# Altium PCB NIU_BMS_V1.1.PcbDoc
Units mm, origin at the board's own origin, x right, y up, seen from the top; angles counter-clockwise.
Board outline 49.68 x 32.61 mm, 2 copper layers (Top Layer, Bottom Layer); 39 components, 16 nets, 111 pads, 19 vias.
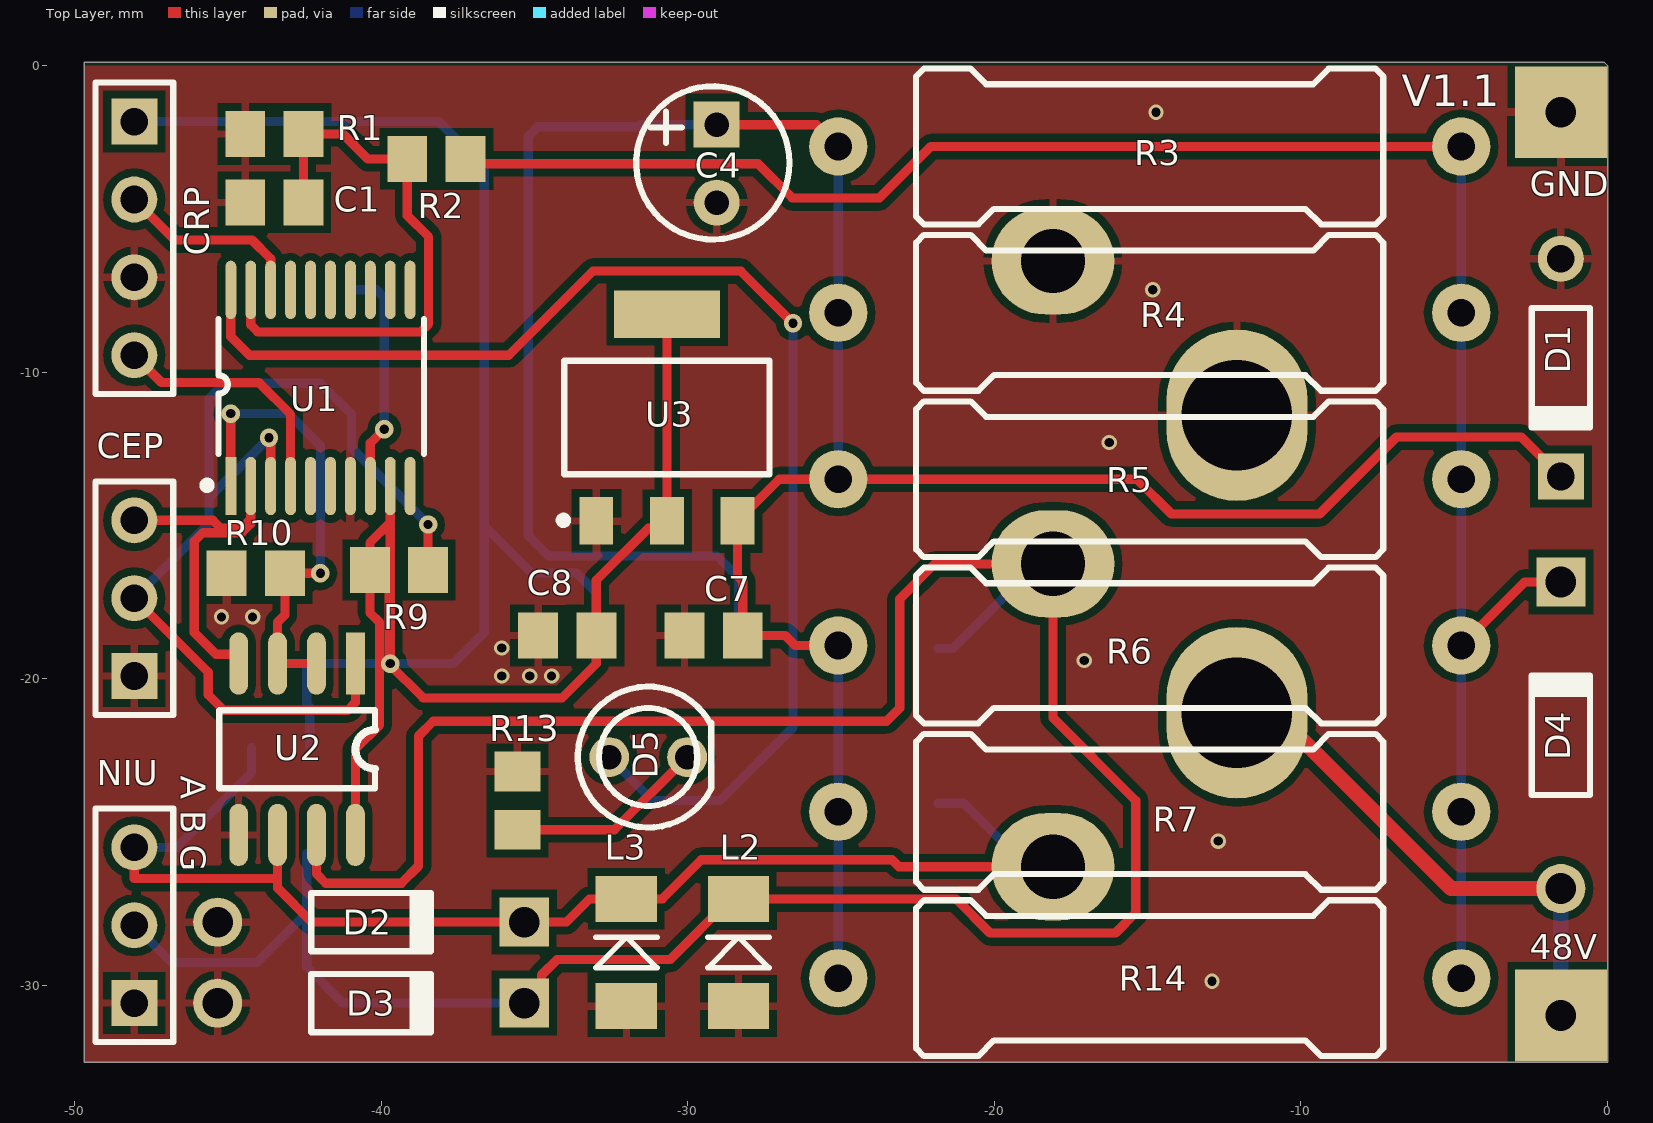
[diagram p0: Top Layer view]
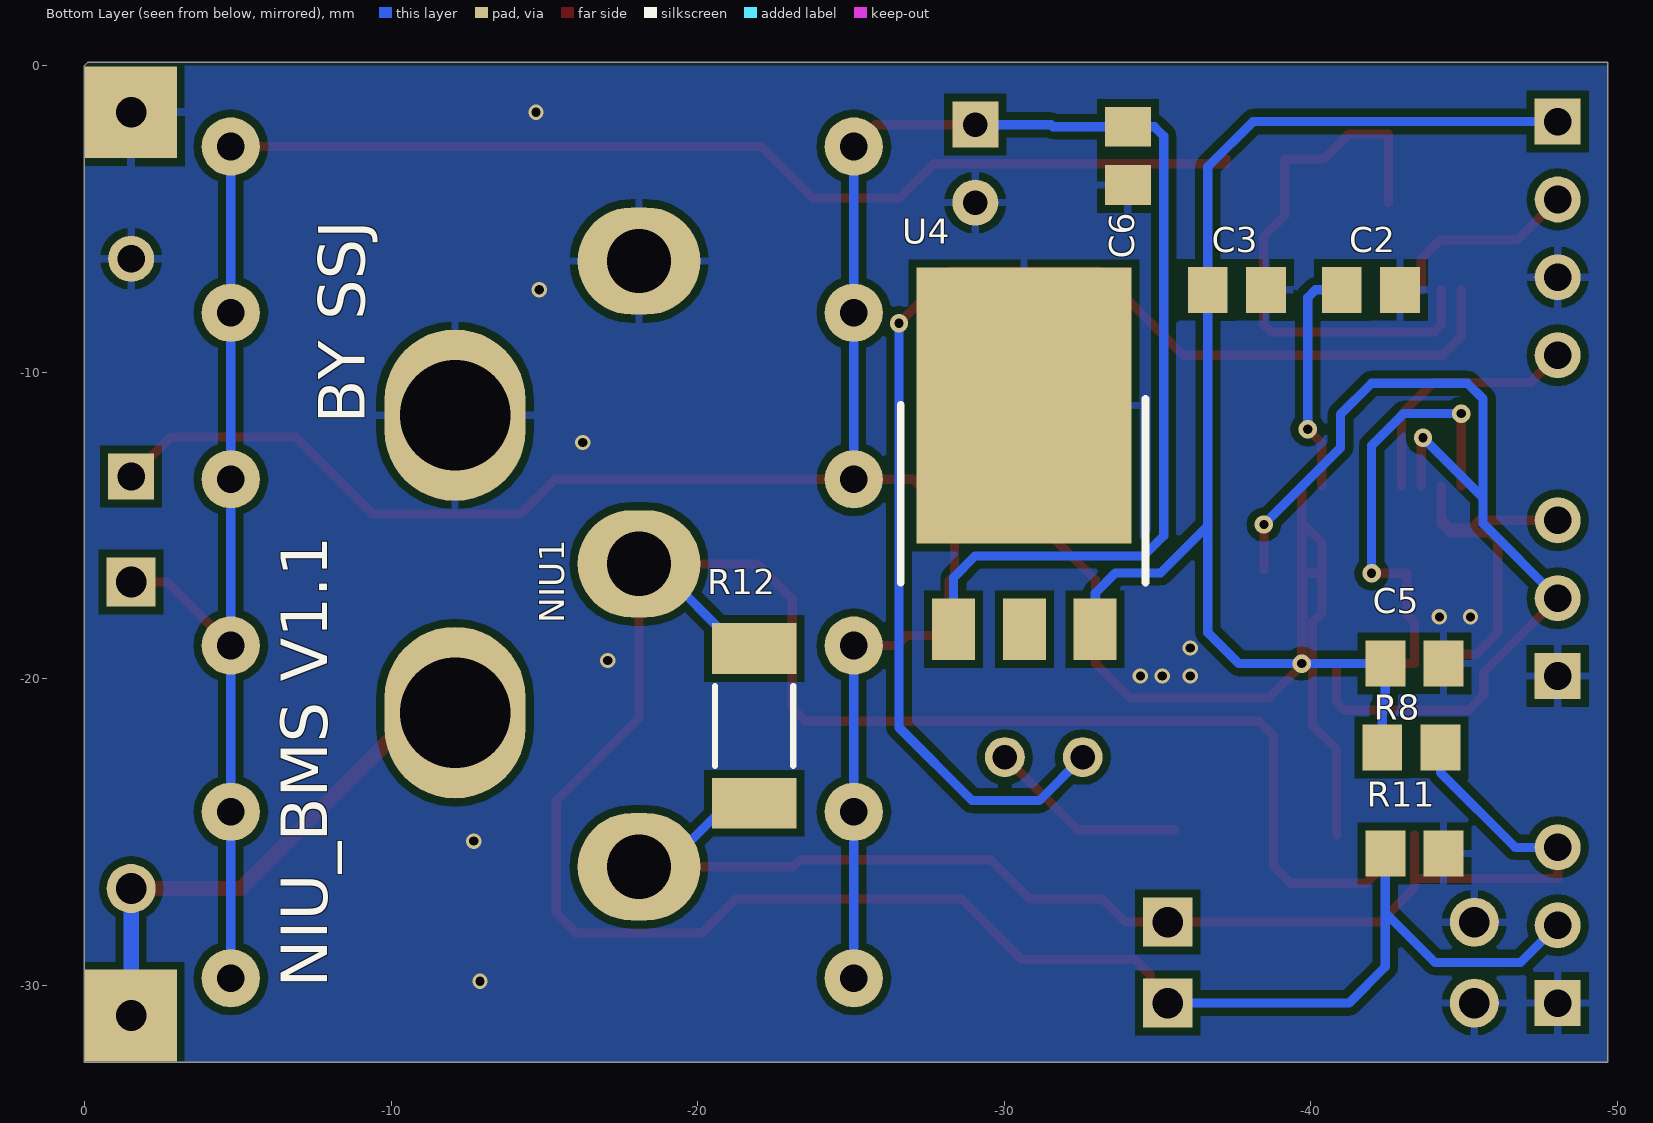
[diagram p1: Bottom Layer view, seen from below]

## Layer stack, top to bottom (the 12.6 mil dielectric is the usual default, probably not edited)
Top Layer: signal copper 0.0356
Dielectric: dielectric 0.32, FR-4, Dk 4.8
Bottom Layer: signal copper 0.0356

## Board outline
0,0 -0.102,0.102 -49.682,0.102 -49.682,-32.512 0,-32.512 0,0

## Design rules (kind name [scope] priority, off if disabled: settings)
Clearance [All] p1: gap=0.254
FabricationTestPointUsage TestPointUsage [All] p1: valid=0 allowmultiple=FALSE
FabricationTestpoint Testpoint [All] p1: side=3 testpointundercomponent=TRUE minsize=1.016 maxsize=2.54 preferedsize=1.524 minholesize=0 maxholesize=1.016 preferedholesize=0.813 testpointgrid=0.025 allowsidetop=TRUE allowsidebottom=TRUE usegrid=TRUE gridtolerance=0
PolygonConnect [All] p1: connectstyle=Relief reliefconductorwidth=0.254 reliefentries=4 polygonreliefangle="90 Angle"
RoutingVias [All] p1: holewidth=0.3 width=0.6 viastyle="Through Hole" minholewidth=0.3 minwidth=0.6 maxholewidth=0.3 maxwidth=0.6
SMDNeckDown [All] p1: percent=99.000
SilkscreenOverComponentPads [All] p1: minsilkscreentomaskgap=0.254
SolderMaskExpansion [All] p1: expansion=0.102
Width 48V [InNet('53V')] p1: maxlimit=3 minlimit=0.254 preferedwidth=0.5 minimp=50.000000 maximp=50.000000 favimp=50.000000
Width Width_1 [All] p2: maxlimit=0.4 minlimit=0.254 preferedwidth=0.3 minimp=50.000000 maximp=50.000000 favimp=50.000000
25 further rules are at their usual default settings.

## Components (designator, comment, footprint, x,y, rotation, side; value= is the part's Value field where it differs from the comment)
48V "TEST" TESTO_3MM -1.524,-30.988 r0 top
C1 "Cap" 0805-2 -43.485,-4.47 r180 top
C2 "Cap" 0805-2 -41.961,-7.315 r0 bottom
C3 "Cap" 0805-2 -37.592,-7.315 r0 bottom
C4 "Cap Pol" C-RB-6 -29.058,-1.93 r270 top
C5 "Cap" 0805-2 -43.383,-19.507 r180 bottom
C6 "Cap" 0805-2 -34.036,-2.946 r270 bottom
C7 "Cap" 0805-2 -29.159,-18.593 r0 top
C8 "Cap" 0805-2 -33.934,-18.593 r180 top
CEP "Header 3" HDR1X3 -48.057,-19.914 r90 top
CRP "SWIM" HDR1X4 -48.057,-1.829 r270 top
D1 "Diode-Z" DIODE-AXL -1.524,-9.855 r270 top
D2 "Diode-Z" DIODE-AXL_10mm -40.335,-27.94 r0 top
D3 "Diode-Z" DIODE-AXL_10mm -40.335,-30.582 r0 top
D4 "Diode" DIODE-AXL_10mm -1.524,-21.844 r90 top
D5 "LED0" LED_A2 -31.293,-22.555 r180 top
GND "TEST" TESTO_3MM -1.524,-1.524 r0 top
L2 "TVS" DIODE-1206 -28.346,-30.683 r90 top
L3 "TVS" DIODE-1206 -32.004,-30.683 r90 top
NIU "CC4" HDR1X3 -48.057,-30.582 r90 top
NIU1 "NIU" NIU -12.09,-16.256 r90 bottom
R1 "Res1" 0805-2 -43.485,-2.235 r0 top
R2 "Res1" 0805-2 -38.202,-3.048 r0 top
R3 "Res1" AXIAL-20-0.8 -14.935,-2.642 r0 top
R4 "Res1" AXIAL-20-0.8 -14.935,-8.067 r0 top
R5 "Res1" AXIAL-20-0.8 -14.935,-13.492 r0 top
R6 "Res1" AXIAL-20-0.8 -14.935,-18.918 r0 top
R7 "Res1" AXIAL-20-0.8 -14.935,-24.343 r0 top
R8 "Res1" 0805-2 -43.282,-22.25 r0 bottom
R9 "Res1" 0805-2 -39.421,-16.459 r0 top
R10 "Res1" 0805-2 -44.094,-16.561 r0 top
R11 "Res1" 0805-2 -43.383,-25.705 r0 bottom
R12 "Res1" 2010 -21.844,-21.539 r90 bottom
R13 "Res1" 0805-2 -35.56,-23.978 r90 top
R14 "Res1" AXIAL-20-0.8 -14.935,-29.769 r0 top
U1 "STM8S103XPXX" "TSSOP20 - duplicate" -44.907,-13.716 r90 top
U2 "TP8485E" SOIC-8P -40.843,-19.507 r180 top
U3 "ASM1117" SOT-223 -30.683,-11.481 r0 top
U4 "78M05" TO-252 -28.346,-18.39 r180 bottom

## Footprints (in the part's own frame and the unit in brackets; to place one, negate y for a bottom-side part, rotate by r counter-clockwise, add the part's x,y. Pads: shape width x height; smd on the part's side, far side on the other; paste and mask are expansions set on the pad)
0805-2 [mm]
  rect 1.3x1.5 smd: 1(-0.95,0) 2(0.95,0)
2010 [mm]
  rect 1.65x2.75 smd: 1(-2.525,0) 2(2.525,0)
  silkscreen extent -1.3,-1.27 1.3,1.27, body extent -2.1,-1.35 2.1,1.35, height 0.6
AXIAL-20-0.8 [mm]
  round 1.9 hole 0.9: 1(-10.16,0) 2(10.16,0)
  silkscreen extent -7.62,-2.54 7.62,2.54, body extent -10.36,-2.46 10.36,2.53, height 4.98
C-RB-6 [mm]
  rect 1.5x1.5 hole 0.8: 1(0,0)
  round 1.5 hole 0.8: 2(2.54,0)
  silkscreen extent -1.26,-2.62 3.74,2.37
DIODE-1206 [mm]
  rect 1.5x2 smd: 1(0,0) 2(3.5,0)
  silkscreen extent 1.25,-1 2.25,1
DIODE-AXL [mm]
  round 1.5 hole 0.9: 1(-3.55,0)
  rect 1.5x1.5 hole 0.9: 2(3.55,0)
  silkscreen extent -1.95,-0.95 2.05,0.95
DIODE-AXL_10mm [mm]
  round 1.6 hole 1: 1(-5,0)
  rect 1.6x1.6 hole 1: 2(5,0)
  silkscreen extent -1.95,-0.95 2.05,0.95
HDR1X3 [mm] "Connector; Header; 3 Position"
  rect 1.5x1.5 hole 0.9: 1(0,0)
  round 1.5 hole 0.9: 2(2.54,0) 3(5.08,0)
  silkscreen extent -1.27,-1.27 6.35,1.27
HDR1X4 [mm] "Connector; Header; 4 Position"
  rect 1.5x1.5 hole 0.9: 1(0,0)
  round 1.5 hole 0.9: 2(2.54,0) 3(5.08,0) 4(7.62,0)
  silkscreen extent -1.27,-1.27 8.89,1.27
LED_A2 [mm]
  round 1.3 hole 0.8: 1(1.27,0) 2(-1.27,0)
  silkscreen extent -2.06,-2.3 2.3,2.3
NIU [mm]
  oval 5.6x4.6 hole 3.6: 1(-4.85,0) 2(4.85,0)
  oval 3.5x4 hole 2.1: 3(-9.88,-6) 4(0,-6) 5(9.88,-6)
SOIC-8P [mil]
  rect 24x80 smd mask+3: 1(0,0)
  oval 24x80 smd mask+3: 2(50,0) 3(100,0) 4(150,0) 5(150,220) 6(100,220) 7(50,220) 8(0,220)
  silkscreen extent -25,60 175,160
SOT-223 [mm]
  rect 1.1x1.55 smd: 1(-2.3,-3.375) 2(0,-3.375) 3(2.3,-3.375)
  rect 3.45x1.55 smd: 4(0,3.375)
  silkscreen extent -3.5,-3.48 3.35,1.85, body extent -3.3,-3.94 3.3,3.43, height 0.8
TESTO_3MM [mm]
  rect 3x3 hole 1: 1(0,0)
TO-252 [mm]
  rect 1.4x2 smd: 1(0,0) 2(2.311,0) 3(4.623,0)
  rect 7x9 smd: 4(2.3,7.3)
  silkscreen extent -1.72,1.52 6.26,7.51
"TSSOP20 - duplicate" [mm] "20-pin, 4.40 mm body, 0.65 mm pitch"
  rect 1.9x0.356 smd: 1(0,0)
  oval 1.9x0.356 smd: 2(0,-0.65) 3(0,-1.3) 4(0,-1.95) 5(0,-2.6) 6(0,-3.25) 7(0,-3.9) 8(0,-4.55) 9(0,-5.2) 10(0,-5.85) 11(6.4,-5.85) 12(6.4,-5.2) 13(6.4,-4.55) 14(6.4,-3.9) 15(6.4,-3.25) 16(6.4,-2.6) 17(6.4,-1.95) 18(6.4,-1.3) 19(6.4,-0.65) 20(6.4,0)
  silkscreen extent -0.1,-6.3 5.45,0.9

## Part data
48V GND: library part TES, "测试"
C1 C2 C3 C5 C6 C7 C8: "无极性"
C4: "极性电解电容"
CEP: "Header, 3-Pin"
CRP: library part "Header 4", "Header, 4-Pin"
D1 D2 D3: "稳压二"
D4: library part D, "二极"
D5: "发光二"
L2 L3: library part T, "TVS保护"
NIU: library part "Header 3", "Header, 3-Pin"
NIU1: "µç³Ø½"
R1 R2 R3 R4 R5 R6 R7 R8 R9 R10 R11 R12 R13 R14: "ÌùÆ¬µ"
U1: library part STM8S103F2P6, "ST 8-bit  Microcontroller"
U3: library part A, "3.3VÎÈÑ¹Ð"
U4: "5V 0.5A"

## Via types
v1: diameter 0.5, hole 0.3, Top Layer to Bottom Layer, 12 vias
v2: diameter 0.6, hole 0.3, Top Layer to Bottom Layer, 7 vias

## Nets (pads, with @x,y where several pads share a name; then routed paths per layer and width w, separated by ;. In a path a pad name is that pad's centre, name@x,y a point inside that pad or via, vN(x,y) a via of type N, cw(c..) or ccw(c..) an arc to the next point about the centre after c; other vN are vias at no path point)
5V: C3.2 C5.1 C8.1 CRP.1 R8.2 R9.1 U1.9 U2.8 U3.2 U3.4 U4.3 | length 82.7
  Top Layer w0.3: U2.8 -40.843,-22.301 -40.056,-21.514 -40.056,-18.161 -40.371,-17.846 R9.1@-40.371,-16.561 ; v2(-39.707,-19.507) -39.707,-14.907 ; U1.9 -39.707,-14.907 ; U3.4 U3.2 -30.683,-15.088 -31.283,-15.088 -32.984,-16.789 C8.1 -32.984,-19.507 -34.102,-20.625 -38.633,-20.625 -39.751,-19.507 -39.751,-16.561 R9.1@-40.371,-16.561 ; R9.1@-40.371,-16.561 R9.1 -40.371,-15.57 -39.707,-14.907
  Bottom Layer w0.3: CRP.1 -38.115,-1.829 -36.642,-3.302 C3.2 -36.642,-15.01 ; R8.2 -42.332,-20.93 -42.433,-20.828 C5.1 v2(-39.707,-19.507) -37.658,-19.507 -36.642,-18.491 -36.642,-15.01 ; U4.3 -32.969,-17.208 -33.63,-16.548 -35.104,-16.548 -36.642,-15.01
8V: C4.1 C6.1 C7.2 D1.2 R3.1 R4.1 R5.1 R6.1 R7.1 R14.1 U3.3 U4.1 | length 90.9
  Top Layer w0.3: C4.1 -25.806,-1.93 R3.1 ; R6.1 -26.497,-18.918 -26.822,-18.593 C7.2 -28.209,-16.815 -28.383,-16.641 U3.3 -27.02,-13.492 R5.1 -15.362,-13.492 -14.224,-14.63 -9.398,-14.63 -6.883,-12.116 -2.813,-12.116 D1.2
  Bottom Layer w0.3: C4.1 -31.532,-1.93 -31.598,-1.996 C6.1 -34.9,-1.996 -35.204,-2.301 -35.204,-15.34 -34.55,-15.994 -29.058,-15.994 -28.346,-16.705 U4.1 ; R14.1 R7.1 R6.1 ; R5.1 R4.1 R3.1
53V: 48V.1 D4.1 NIU1.1 | length 17.1
  Top Layer w0.5: NIU1.1 -10.847,-21.106 -5.109,-26.844 D4.1
  Bottom Layer w0.5: 48V.1 D4.1
A: D2.2 L3.2 NIU1.3 NIU.3 R8.1 R12.1 U2.6 | length 44.4
  Top Layer w0.3: NIU.3 -48.057,-26.518 -43.383,-26.518 ; U2.6 -43.383,-26.518 ; NIU1.3 -23.115,-26.136 -23.343,-25.908 -29.56,-25.908 -30.836,-27.183 L3.2 -33.205,-27.183 -33.962,-27.94 D2.2 -42.266,-27.94 -43.383,-26.822 -43.383,-26.518
  Bottom Layer w0.3: NIU.3 -46.67,-25.502 -44.232,-23.063 R8.1 ; R12.1 -21.006,-24.064 -18.934,-26.136 NIU1.3
B: D3.2 L2.2 NIU1.4 NIU.2 R11.2 R12.2 U2.7 | length 92.4
  Top Layer w0.3: U2.7 -42.113,-26.365 -41.808,-26.67 -39.345,-26.67 -38.786,-26.111 -38.786,-21.869 -38.303,-21.387 -23.52,-21.387 -23.089,-20.955 -23.089,-17.399 -21.946,-16.256 NIU1.4 -18.09,-21.28 -15.392,-23.978 -15.392,-27.635 -16.053,-28.296 -20.142,-28.296 -21.255,-27.183 L2.2 -28.6,-27.183 -30.576,-29.159 -34.265,-29.159 -34.773,-29.667 -34.773,-30.582 D3.2
  Bottom Layer w0.3: NIU.2 -46.838,-29.261 -44.059,-29.261 -42.433,-27.635 ; R11.2 -42.433,-27.635 ; D3.2 -41.25,-30.582 -42.433,-29.398 -42.433,-27.635 ; R12.2 -21.361,-19.014 -18.603,-16.256 NIU1.4
D1: CRP.2 U1.18 | length 6.3
  Top Layer w0.3: CRP.2 -46.736,-5.69 -44.217,-5.69 -43.607,-6.299 U1.18
D53V: D4.2 R2.2 R3.2 R4.2 R5.2 R6.2 R7.2 R14.2 | length 65
  Top Layer w0.3: R2.2 -37.252,-3.2 -27.711,-3.2 -26.594,-4.318 -23.749,-4.318 -22.073,-2.642 R3.2 ; R6.2 -2.701,-16.844 D4.2
  Bottom Layer w0.3: R14.2 R7.2 R6.2 R5.2 R4.2 R3.2
DIR: R10.2 U1.1 U2.2 U2.3 | length 15.4
  Top Layer w0.3: U1.1 v2(-44.907,-11.354) ; U2.2 U2.3 -43.383,-18.161 -43.144,-17.922 R10.2 v2(-41.986,-16.561)
  Bottom Layer w0.3: v2(-44.907,-11.354) -43.028,-11.354 -41.986,-12.395 v2(-41.986,-16.561)
GND: C1.2 C2.1 C3.1 C4.2 C5.2 C6.2 C7.1 C8.2 CEP.1 CRP.3 D1.1 D2.1 D3.1 GND.1 L2.1 L3.1 NIU1.2 NIU1.5 NIU.1 R1.1 R10.1 R11.1 R13.2 U1.7 U2.5 U3.1 U4.4
  other v1: -12.903,-29.87 -12.7,-25.298 -36.068,-19.914 -35.154,-19.914 -34.442,-19.914 -17.069,-19.406 -36.068,-18.999 -45.212,-17.983 -44.196,-17.983 -16.256,-12.294 -14.834,-7.315 -14.732,-1.524
GV: C1.1 R1.2 R2.1 U1.19 | length 18.8
  Top Layer w0.3: U1.19 -44.257,-8.458 -44.029,-8.687 -38.71,-8.687 -38.456,-8.433 -38.456,-5.588 -39.152,-4.892 R2.1 -40.437,-3.048 -41.25,-2.235 R1.2 C1.1
LED: D5.1 U1.20 | length 42.7
  Top Layer w0.3: U1.20 -44.907,-8.839 -44.298,-9.449 -35.839,-9.449 -33.096,-6.706 -28.27,-6.706 v2(-26.568,-8.407)
  Bottom Layer w0.3: D5.1 -31.14,-23.978 -28.956,-23.978 -26.568,-21.59 v2(-26.568,-8.407)
NetC2_2: C2.2 U1.8 | length 7.5
  Top Layer w0.3: U1.8 -40.357,-12.316 v2(-39.903,-11.862)
  Bottom Layer w0.3: C2.2 -40.157,-7.315 -39.903,-7.569 v2(-39.903,-11.862)
NetD5_2: D5.2 R13.1 | length 6.5
  Top Layer w0.3: R13.1 -32.395,-24.928 D5.2
NRST: CRP.4 U1.4 | length 8.2
  Top Layer w0.3: CRP.4 -47.168,-10.338 -43.999,-10.338 -42.957,-11.379 U1.4
RX: CEP.2 R9.2 U1.3 U2.1 | length 33.8
  Top Layer w0.3: CEP.2 -45.644,-19.787 -45.644,-20.523 -45.136,-21.031 -41.097,-21.031 -40.843,-20.777 U2.1 ; v2(-43.663,-12.141) -43.607,-12.197 U1.3 ; R9.2 v2(-38.471,-14.971)
  Bottom Layer w0.3: CEP.2 -45.618,-14.935 -45.618,-14.097 ; v2(-43.663,-12.141) -45.618,-14.097 ; v2(-38.471,-14.971) -40.97,-12.471 -40.97,-11.379 -41.986,-10.363 -45.11,-10.363 -45.618,-10.871 -45.618,-14.097
TX: CEP.3 U1.2 U2.4 | length 12.4
  Top Layer w0.3: CEP.3 -45.491,-14.834 -45.237,-15.088 -44.552,-15.088 -44.257,-14.793 ; U2.4 -44.653,-19.202 -45.39,-19.202 -46.101,-18.491 -46.101,-15.519 -45.822,-15.24 -44.552,-15.24 -44.257,-14.946 -44.257,-14.793 ; U1.2 -44.257,-14.793
pads on no net: U1.5 U1.6 U1.10 U1.11 U1.12 U1.13 U1.14 U1.15 U1.16 U1.17 U4.2

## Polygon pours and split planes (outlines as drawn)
GND on Bottom Layer "Top Layer-No Net" (solid, pour order 4): 0,0 -49.682,0 -49.682,-32.512 0,-32.512
GND on Top Layer "Top Layer-No Net" (solid, pour order 6): 0,0 -49.682,0 -49.682,-32.512 0,-32.512

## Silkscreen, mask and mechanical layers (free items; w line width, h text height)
Top Overlay:
  text "V1.1" at -6.706,-1.321 h1.02
  text "A B G" at -46.533,-23.165 h0.82 r270
Bottom Overlay:
  text "BY SSJ" at -9.144,-11.684 h1.52 r270
  text "NIU_BMS V1.1" at -7.925,-30.074 h1.52 r270
Mechanical 1:
  lines w0.254: -49.682,-32.512 0,-32.512 0,0 -49.682,0 -49.682,-32.512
